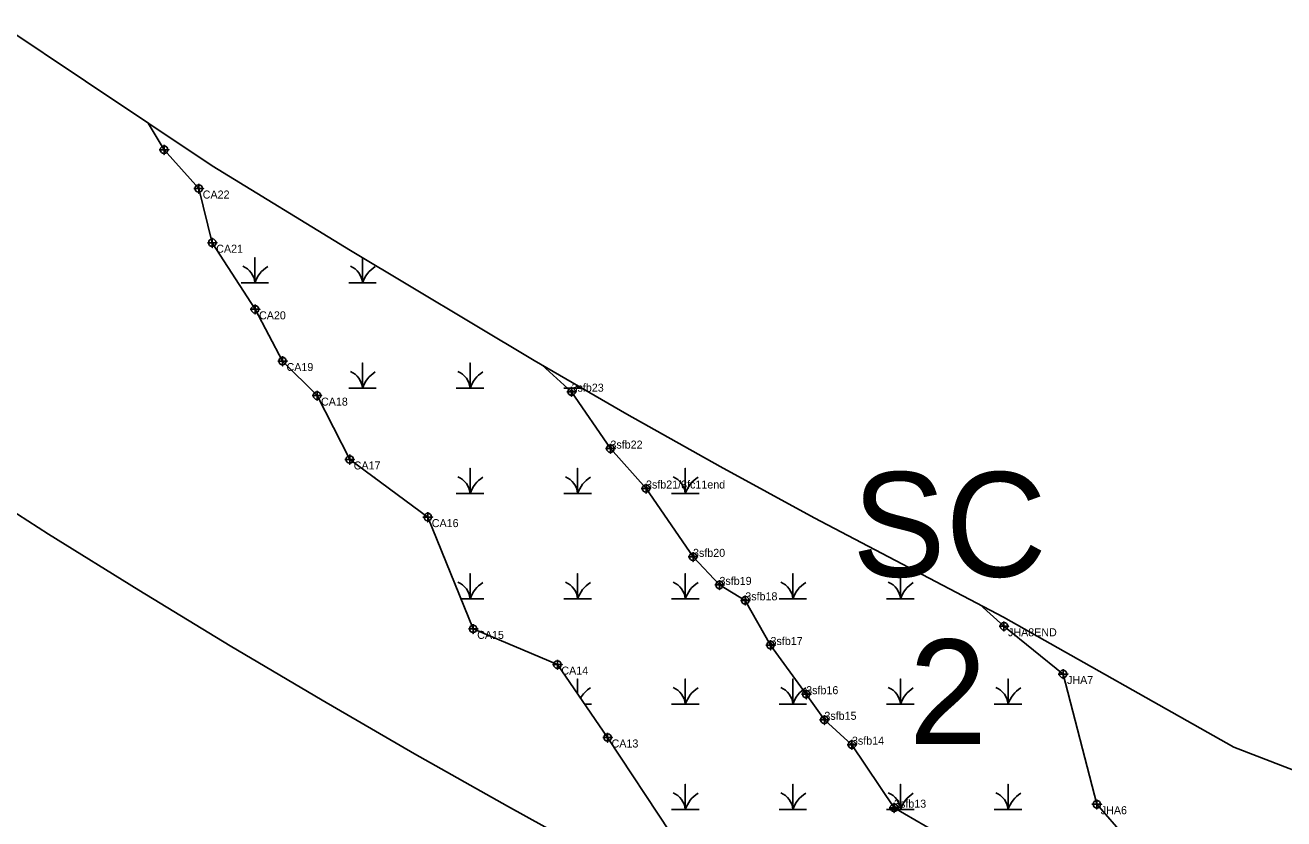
# Model space of a CAD drawing. Extents: x 2071991 to 2268989, y 436479 to 469629.
# Drawn here: x 2096115 to 2096901, y 458974 to 459469 of the extents above; entities that cross this region are included whole.
import ezdxf

# ---------------------------------------------------------------- set-up
doc = ezdxf.new("R2010")
doc.units = 0
for name, color, linetype in [('approx_PSA', 7, 'Continuous'), ('Default', 7, 'Continuous'), ('Exist Environmental Wetland Boundary', 7, 'Continuous'), ('Exist Environmental Wetland Boundary Cogo Comment', 7, 'Continuous'), ('Exist Environmental Wetland Boundary Cogo Point CELL', 7, 'Continuous'), ('Exist Hydro Jurisdictional Stream or Body of Water NEU Mitigable', 7, 'Continuous'), ('Exist Hydro Jurisdictional Stream or Body of Water NEU Mitigable Cogo Comment', 7, 'Continuous'), ('Exist Hydro Jurisdictional Stream or Body of Water NEU Mitigable Cogo Point CELL', 7, 'Continuous'), ('Exist Hydro Swamp or Marsh', 7, 'Continuous')]:
    doc.layers.add(name, color=color, linetype=linetype)

msp = doc.modelspace()

# ---------------------------------------------------------------- linework, layer by layer
at = {"layer": 'approx_PSA'}
for p, q in [((2096100.28, 459469.36), (2096152.49, 459434.39)), ((2096152.49, 459434.39), (2096231.68, 459381.59)), ((2096231.68, 459381.59), (2096318.13, 459328.66)), ((2096318.13, 459328.66), (2096432.8, 459259.93)), ((2096432.8, 459259.93), (2096490.71, 459226.54)), ((2096490.71, 459226.54), (2096549, 459193.82)), ((2096549, 459193.82), (2096607.65, 459161.77)), ((2096129.53, 459151.6), (2096073.58, 459187.29)), ((2096607.65, 459161.77), (2096726.04, 459099.67)), ((2096185.85, 459116.52), (2096129.53, 459151.6)), ((2096242.89, 459081.85), (2096185.85, 459116.52)), ((2096726.04, 459099.67), (2096869.76, 459018.53)), ((2096300.31, 459047.8), (2096242.89, 459081.85)), ((2096358.09, 459014.38), (2096300.31, 459047.8)), ((2096416.23, 458981.59), (2096358.09, 459014.38)), ((2096869.76, 459018.53), (2096932.31, 458994.44)), ((2096474.73, 458949.44), (2096416.23, 458981.59))]:
    msp.add_line(p, q, dxfattribs=at)
at = {"layer": 'Exist Environmental Wetland Boundary'}
for points in [[(2096191.79, 459408.18), (2096201.66, 459391.57), (2096223.32, 459367.35), (2096231.73, 459333.52), (2096258.48, 459291.91), (2096275.64, 459259.61), (2096297.19, 459238.03), (2096317.6, 459198.16), (2096366.38, 459162.16), (2096394.71, 459092.36), (2096447.32, 459070.06), (2096478.67, 459024.53), (2096517.89, 458965.03)], [(2096801.99, 458962.51), (2096784.25, 458982.86), (2096763.16, 459064.18), (2096726.28, 459093.98), (2096711.1, 459107.5)]]:
    msp.add_lwpolyline(points, dxfattribs=at)
at = {"layer": 'Exist Environmental Wetland Boundary Cogo Point CELL'}
for points in [[(2096201.66, 459394.57), (2096201.66, 459388.57), (2096201.66, 459391.57), (2096204.66, 459391.57), (2096198.66, 459391.57)], [(2096223.32, 459370.35), (2096223.32, 459364.35), (2096223.32, 459367.35), (2096226.32, 459367.35), (2096220.32, 459367.35)], [(2096231.73, 459336.52), (2096231.73, 459330.52), (2096231.73, 459333.52), (2096234.73, 459333.52), (2096228.73, 459333.52)], [(2096258.48, 459294.91), (2096258.48, 459288.91), (2096258.48, 459291.91), (2096261.48, 459291.91), (2096255.48, 459291.91)], [(2096275.64, 459262.61), (2096275.64, 459256.61), (2096275.64, 459259.61), (2096278.64, 459259.61), (2096272.64, 459259.61)], [(2096297.19, 459241.03), (2096297.19, 459235.03), (2096297.19, 459238.03), (2096300.19, 459238.03), (2096294.19, 459238.03)], [(2096317.6, 459201.16), (2096317.6, 459195.16), (2096317.6, 459198.16), (2096320.6, 459198.16), (2096314.6, 459198.16)], [(2096366.38, 459165.16), (2096366.38, 459159.16), (2096366.38, 459162.16), (2096369.38, 459162.16), (2096363.38, 459162.16)], [(2096394.71, 459095.36), (2096394.71, 459089.36), (2096394.71, 459092.36), (2096397.71, 459092.36), (2096391.71, 459092.36)], [(2096726.28, 459096.98), (2096726.28, 459090.98), (2096726.28, 459093.98), (2096729.28, 459093.98), (2096723.28, 459093.98)], [(2096447.32, 459073.06), (2096447.32, 459067.06), (2096447.32, 459070.06), (2096450.32, 459070.06), (2096444.32, 459070.06)], [(2096763.16, 459067.18), (2096763.16, 459061.18), (2096763.16, 459064.18), (2096766.16, 459064.18), (2096760.16, 459064.18)], [(2096478.67, 459027.53), (2096478.67, 459021.53), (2096478.67, 459024.53), (2096481.67, 459024.53), (2096475.67, 459024.53)], [(2096784.25, 458985.86), (2096784.25, 458979.86), (2096784.25, 458982.86), (2096787.25, 458982.86), (2096781.25, 458982.86)]]:
    msp.add_lwpolyline(points, dxfattribs=at)
for centre in [(2096201.66, 459391.57), (2096223.32, 459367.35), (2096231.73, 459333.52), (2096258.48, 459291.91), (2096275.64, 459259.61), (2096297.19, 459238.03), (2096317.6, 459198.16), (2096366.38, 459162.16), (2096394.71, 459092.36), (2096726.28, 459093.98), (2096447.32, 459070.06), (2096763.16, 459064.18), (2096478.67, 459024.53), (2096784.25, 458982.86)]:
    msp.add_circle(centre, 2.34, dxfattribs=at)
at = {"layer": 'Exist Hydro Jurisdictional Stream or Body of Water NEU Mitigable'}
msp.add_lwpolyline([(2096437.83, 459257.03), (2096456.19, 459240.49), (2096480.46, 459204.95), (2096502.68, 459180.01), (2096532.04, 459137.34), (2096548.57, 459119.82), (2096564.69, 459110.17), (2096580.46, 459082.27), (2096602.73, 459051.57), (2096614.09, 459035.56), (2096631.32, 459020.05), (2096657.61, 458980.69), (2096683.56, 458965.68), (2096684.49, 458948.88), (2096708.15, 458936), (2096719.62, 458916.38), (2096744.57, 458883.08), (2096757.6, 458862.28), (2096773.52, 458838.19), (2096799.03, 458816.48), (2096813.82, 458804.99), (2096819.34, 458797.23), (2096815.73, 458777.28), (2096825.54, 458767.8)], dxfattribs=at)
at = {"layer": 'Exist Hydro Jurisdictional Stream or Body of Water NEU Mitigable Cogo Point CELL'}
for points in [[(2096456.19, 459243.49), (2096456.19, 459237.49), (2096456.19, 459240.49), (2096459.19, 459240.49), (2096453.19, 459240.49)], [(2096480.46, 459207.95), (2096480.46, 459201.95), (2096480.46, 459204.95), (2096483.46, 459204.95), (2096477.46, 459204.95)], [(2096502.68, 459183.01), (2096502.68, 459177.01), (2096502.68, 459180.01), (2096505.68, 459180.01), (2096499.68, 459180.01)], [(2096532.04, 459140.34), (2096532.04, 459134.34), (2096532.04, 459137.34), (2096535.04, 459137.34), (2096529.04, 459137.34)], [(2096548.57, 459122.82), (2096548.57, 459116.82), (2096548.57, 459119.82), (2096551.57, 459119.82), (2096545.57, 459119.82)], [(2096564.69, 459113.17), (2096564.69, 459107.17), (2096564.69, 459110.17), (2096567.69, 459110.17), (2096561.69, 459110.17)], [(2096580.46, 459085.27), (2096580.46, 459079.27), (2096580.46, 459082.27), (2096583.46, 459082.27), (2096577.46, 459082.27)], [(2096602.73, 459054.57), (2096602.73, 459048.57), (2096602.73, 459051.57), (2096605.73, 459051.57), (2096599.73, 459051.57)], [(2096614.09, 459038.56), (2096614.09, 459032.56), (2096614.09, 459035.56), (2096617.09, 459035.56), (2096611.09, 459035.56)], [(2096631.32, 459023.05), (2096631.32, 459017.05), (2096631.32, 459020.05), (2096634.32, 459020.05), (2096628.32, 459020.05)], [(2096657.61, 458983.69), (2096657.61, 458977.69), (2096657.61, 458980.69), (2096660.61, 458980.69), (2096654.61, 458980.69)]]:
    msp.add_lwpolyline(points, dxfattribs=at)
for centre in [(2096456.19, 459240.49), (2096480.46, 459204.95), (2096502.68, 459180.01), (2096532.04, 459137.34), (2096548.57, 459119.82), (2096564.69, 459110.17), (2096580.46, 459082.27), (2096602.73, 459051.57), (2096614.09, 459035.56), (2096631.32, 459020.05), (2096657.61, 458980.69)]:
    msp.add_circle(centre, 2.34, dxfattribs=at)
at = {"layer": 'Exist Hydro Swamp or Marsh'}
msp.add_line((2096464.38, 459045.29), (2096468.58, 459045.29), dxfattribs=at)
for points in [[(2096249.77, 459308.41), (2096258.37, 459308.41), (2096258.37, 459324.19), (2096258.37, 459308.41), (2096266.97, 459308.41)], [(2096316.97, 459308.41), (2096325.57, 459308.41), (2096325.57, 459324.19), (2096325.57, 459308.41), (2096334.18, 459308.41)], [(2096316.97, 459242.63), (2096325.57, 459242.63), (2096325.57, 459258.41), (2096325.57, 459242.63), (2096334.18, 459242.63)], [(2096384.18, 459242.63), (2096392.78, 459242.63), (2096392.78, 459258.41), (2096392.78, 459242.63), (2096401.38, 459242.63)], [(2096451.38, 459242.63), (2096459.98, 459242.63), (2096459.98, 459244.26)], [(2096459.98, 459244.26), (2096459.98, 459242.63), (2096462.81, 459242.63)], [(2096325.57, 459192.27), (2096325.57, 459192.63), (2096325.57, 459192.27)], [(2096384.18, 459176.85), (2096392.78, 459176.85), (2096392.78, 459192.63), (2096392.78, 459176.85), (2096401.38, 459176.85)], [(2096451.38, 459176.85), (2096459.98, 459176.85), (2096459.98, 459192.63), (2096459.98, 459176.85), (2096468.58, 459176.85)], [(2096518.58, 459176.85), (2096527.18, 459176.85), (2096527.18, 459192.63), (2096527.18, 459176.85), (2096535.79, 459176.85)], [(2096387.11, 459111.07), (2096392.78, 459111.07), (2096392.78, 459126.85), (2096392.78, 459111.07), (2096401.38, 459111.07)], [(2096451.38, 459111.07), (2096459.98, 459111.07), (2096459.98, 459126.85), (2096459.98, 459111.07), (2096468.58, 459111.07)], [(2096518.58, 459111.07), (2096527.18, 459111.07), (2096527.18, 459126.85), (2096527.18, 459111.07), (2096535.79, 459111.07)], [(2096585.79, 459111.07), (2096594.39, 459111.07), (2096594.39, 459126.85), (2096594.39, 459111.07), (2096602.99, 459111.07)], [(2096652.99, 459111.07), (2096661.59, 459111.07), (2096661.59, 459126.85), (2096661.59, 459111.07), (2096670.19, 459111.07)], [(2096459.98, 459051.68), (2096459.98, 459061.07), (2096459.98, 459051.68)], [(2096518.58, 459045.29), (2096527.18, 459045.29), (2096527.18, 459061.07), (2096527.18, 459045.29), (2096535.79, 459045.29)], [(2096585.79, 459045.29), (2096594.39, 459045.29), (2096594.39, 459061.07), (2096594.39, 459045.29), (2096602.99, 459045.29)], [(2096652.99, 459045.29), (2096661.59, 459045.29), (2096661.59, 459061.07), (2096661.59, 459045.29), (2096670.19, 459045.29)], [(2096720.19, 459045.29), (2096728.79, 459045.29), (2096728.79, 459061.07), (2096728.79, 459045.29), (2096737.4, 459045.29)], [(2096518.58, 458979.51), (2096527.18, 458979.51), (2096527.18, 458995.29), (2096527.18, 458979.51), (2096535.79, 458979.51)], [(2096585.79, 458979.51), (2096594.39, 458979.51), (2096594.39, 458995.29), (2096594.39, 458979.51), (2096602.99, 458979.51)], [(2096652.99, 458979.51), (2096661.59, 458979.51), (2096661.59, 458995.29), (2096661.59, 458979.51), (2096670.19, 458979.51)], [(2096720.19, 458979.51), (2096728.79, 458979.51), (2096728.79, 458995.29), (2096728.79, 458979.51), (2096737.4, 458979.51)]]:
    msp.add_lwpolyline(points, dxfattribs=at)
for centre, radius, start, end in [((2096246.1, 459307.52), 12.3, 4.14034, 67.53497), ((2096276.61, 459302.35), 19.22, 122.12745, 161.62219), ((2096313.31, 459307.52), 12.3, 4.14034, 67.53497), ((2096343.82, 459302.35), 19.22, 122.12745, 161.62219), ((2096313.31, 459241.74), 12.3, 4.14034, 67.53497), ((2096343.82, 459236.57), 19.22, 122.12745, 161.62219), ((2096380.51, 459241.74), 12.3, 4.14034, 67.53497), ((2096411.02, 459236.57), 19.22, 122.12745, 161.62219), ((2096447.71, 459241.74), 12.3, 4.14034, 12.5349), ((2096478.22, 459236.57), 19.22, 157.35217, 161.62219), ((2096343.82, 459170.79), 19.22, 122.12745, 123.94862), ((2096380.51, 459175.96), 12.3, 4.14034, 67.53497), ((2096411.02, 459170.79), 19.22, 122.12745, 161.62219), ((2096447.71, 459175.96), 12.3, 4.14034, 67.53497), ((2096478.22, 459170.79), 19.22, 122.12745, 161.62219), ((2096514.92, 459175.96), 12.3, 4.14034, 67.53497), ((2096545.43, 459170.79), 19.22, 122.12745, 161.62219), ((2096380.51, 459110.18), 12.3, 4.14034, 67.53497), ((2096411.02, 459105.01), 19.22, 122.12745, 161.62219), ((2096447.71, 459110.18), 12.3, 4.14034, 67.53497), ((2096478.22, 459105.01), 19.22, 122.12745, 161.62219), ((2096514.92, 459110.18), 12.3, 4.14034, 67.53497), ((2096545.43, 459105.01), 19.22, 122.12745, 161.62219), ((2096582.12, 459110.18), 12.3, 4.14034, 67.53497), ((2096612.63, 459105.01), 19.22, 122.12745, 161.62219), ((2096649.32, 459110.18), 12.3, 4.14034, 67.53497), ((2096679.83, 459105.01), 19.22, 122.12745, 161.62219), ((2096478.22, 459039.23), 19.22, 122.12745, 149.01758), ((2096514.92, 459044.4), 12.3, 4.14034, 67.53497), ((2096545.43, 459039.23), 19.22, 122.12745, 161.62219), ((2096582.12, 459044.4), 12.3, 4.14034, 67.53497), ((2096612.63, 459039.23), 19.22, 122.12745, 161.62219), ((2096649.32, 459044.4), 12.3, 4.14034, 67.53497), ((2096679.83, 459039.23), 19.22, 122.12745, 161.62219), ((2096716.53, 459044.4), 12.3, 4.14034, 67.53497), ((2096747.04, 459039.23), 19.22, 122.12745, 161.62219), ((2096514.92, 458978.62), 12.3, 4.14034, 67.53497), ((2096545.43, 458973.45), 19.22, 122.12745, 161.62219), ((2096582.12, 458978.62), 12.3, 4.14034, 67.53497), ((2096612.63, 458973.45), 19.22, 122.12745, 161.62219), ((2096649.32, 458978.62), 12.3, 4.14034, 67.53497), ((2096679.83, 458973.45), 19.22, 122.12745, 161.62219), ((2096716.53, 458978.62), 12.3, 4.14034, 67.53497), ((2096747.04, 458973.45), 19.22, 122.12745, 161.62219)]:
    msp.add_arc(centre, radius, start, end, dxfattribs=at)

# ---------------------------------------------------------------- texts
at = {"layer": 'Default'}
for s, p in [('SC', (2096631.53, 459124.93)), ('2', (2096667.01, 459020.39))]:
    msp.add_text(s, height=65.34, dxfattribs=at).set_placement(p)
at = {"layer": 'Exist Environmental Wetland Boundary Cogo Comment'}
for s, p in [('CA22', (2096225.82, 459361.1)), ('CA21', (2096234.23, 459327.27)), ('CA20', (2096260.98, 459285.66)), ('CA19', (2096278.14, 459253.36)), ('CA18', (2096299.69, 459231.78)), ('CA17', (2096320.1, 459191.91)), ('CA16', (2096368.88, 459155.91)), ('CA15', (2096397.21, 459086.11)), ('JHA8END', (2096728.78, 459087.73)), ('CA14', (2096449.82, 459063.81)), ('JHA7', (2096765.66, 459057.93)), ('CA13', (2096481.17, 459018.28)), ('JHA6', (2096786.75, 458976.61))]:
    msp.add_text(s, height=5, dxfattribs=at).set_placement(p)
at = {"layer": 'Exist Hydro Jurisdictional Stream or Body of Water NEU Mitigable Cogo Comment'}
for s, p in [('3sfb23', (2096456.19, 459240.49)), ('3sfb22', (2096480.46, 459204.95)), ('3sfb21/3fc11end', (2096502.68, 459180.01)), ('3sfb20', (2096532.04, 459137.34)), ('3sfb19', (2096548.57, 459119.82)), ('3sfb18', (2096564.69, 459110.17)), ('3sfb17', (2096580.46, 459082.27)), ('3sfb16', (2096602.73, 459051.57)), ('3sfb15', (2096614.09, 459035.56)), ('3sfb14', (2096631.32, 459020.05)), ('3sfb13', (2096657.61, 458980.69))]:
    msp.add_text(s, height=5, dxfattribs=at).set_placement(p)

doc.saveas('drawing.dxf')
